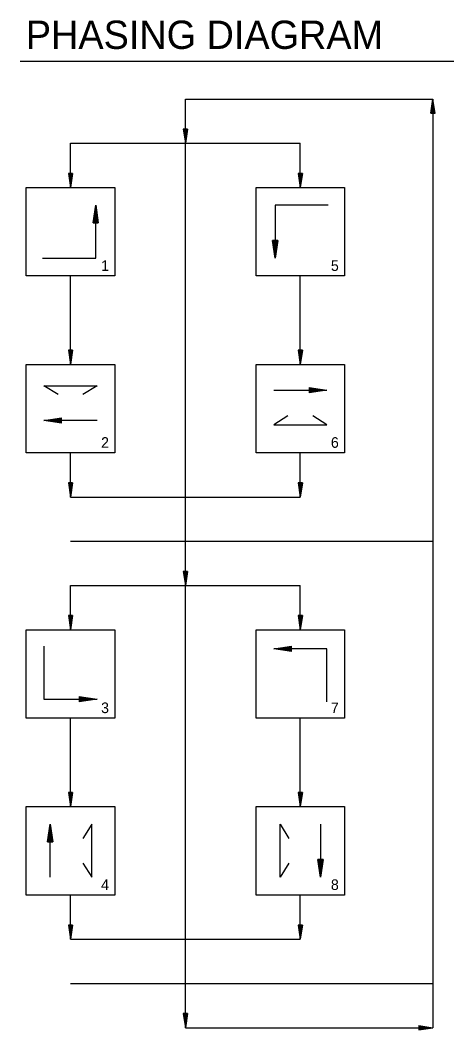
# Model space of a CAD drawing. Extents: x -19.5 to 29.5, y 0.4 to 10.6.
# Drawn here: x 1.101 to 3.145, y 5.812 to 10.569 of the extents above; entities that cross this region are included whole.
import ezdxf

# ---------------------------------------------------------------- set-up
doc = ezdxf.new("R2010")
doc.units = 0
for name, color, linetype in [('R_Draft', 7, 'Continuous'), ('T_Drafting', 7, 'Continuous'), ('T_Notes', 7, 'Continuous')]:
    doc.layers.add(name, color=color, linetype=linetype)

msp = doc.modelspace()

# ---------------------------------------------------------------- linework, layer by layer
at = {"layer": 'R_Draft'}
for p, q in [((3.0364, 10.1308), (3.0464, 10.1974)), ((3.0381, 10.1308), (3.0464, 10.1863)), ((3.0564, 10.1308), (3.0464, 10.1974)), ((3.0548, 10.1308), (3.0464, 10.1863)), ((3.0398, 10.1308), (3.0464, 10.1748)), ((3.0415, 10.1308), (3.0464, 10.1637)), ((3.0432, 10.1308), (3.0464, 10.1524)), ((3.0449, 10.1308), (3.0464, 10.1413)), ((3.0531, 10.1308), (3.0464, 10.1748)), ((3.0514, 10.1308), (3.0464, 10.1637)), ((3.0497, 10.1308), (3.0464, 10.1524)), ((3.048, 10.1308), (3.0464, 10.1413)), ((3.0364, 10.1308), (3.0564, 10.1308)), ((1.8698, 10.0558), (1.8798, 9.9891)), ((1.8898, 10.0558), (1.8698, 10.0558)), ((1.8714, 10.0558), (1.8798, 10.0002)), ((1.8731, 10.0558), (1.8798, 10.0117)), ((1.8748, 10.0558), (1.8798, 10.0228)), ((1.8765, 10.0558), (1.8798, 10.0341)), ((1.8782, 10.0558), (1.8798, 10.0452)), ((1.8898, 10.0558), (1.8798, 9.9891)), ((1.883, 10.0558), (1.8798, 10.0341)), ((1.8864, 10.0558), (1.8798, 10.0117)), ((1.8881, 10.0558), (1.8798, 10.0002)), ((1.8847, 10.0558), (1.8798, 10.0228)), ((1.8813, 10.0558), (1.8798, 10.0452)), ((1.3281, 9.8474), (1.3381, 9.7808)), ((1.3481, 9.8474), (1.3281, 9.8474)), ((1.3298, 9.8474), (1.3381, 9.7919)), ((1.3315, 9.8474), (1.3381, 9.8034)), ((1.3331, 9.8474), (1.3381, 9.8145)), ((1.3348, 9.8474), (1.3381, 9.8258)), ((1.3365, 9.8474), (1.3381, 9.8369)), ((1.3481, 9.8474), (1.3381, 9.7808)), ((1.3413, 9.8474), (1.3381, 9.8258)), ((1.3447, 9.8474), (1.3381, 9.8034)), ((1.3464, 9.8474), (1.3381, 9.7919)), ((1.3431, 9.8474), (1.3381, 9.8145)), ((1.3397, 9.8474), (1.3381, 9.8369)), ((2.4114, 9.8474), (2.4214, 9.7808)), ((2.4314, 9.8474), (2.4114, 9.8474)), ((2.4131, 9.8474), (2.4214, 9.7919)), ((2.4148, 9.8474), (2.4214, 9.8034)), ((2.4165, 9.8474), (2.4214, 9.8145)), ((2.4182, 9.8474), (2.4214, 9.8258)), ((2.4199, 9.8474), (2.4214, 9.8369)), ((2.4314, 9.8474), (2.4214, 9.7808)), ((2.4247, 9.8474), (2.4214, 9.8258)), ((2.4281, 9.8474), (2.4214, 9.8034)), ((2.4298, 9.8474), (2.4214, 9.7919)), ((2.4264, 9.8474), (2.4214, 9.8145)), ((2.423, 9.8474), (2.4214, 9.8369)), ((1.3281, 9.0141), (1.3381, 8.9474)), ((1.3481, 9.0141), (1.3281, 9.0141)), ((1.3298, 9.0141), (1.3381, 8.9586)), ((1.3315, 9.0141), (1.3381, 8.97)), ((1.3331, 9.0141), (1.3381, 8.9811)), ((1.3348, 9.0141), (1.3381, 8.9924)), ((1.3365, 9.0141), (1.3381, 9.0036)), ((1.3481, 9.0141), (1.3381, 8.9474)), ((1.3413, 9.0141), (1.3381, 8.9924)), ((1.3447, 9.0141), (1.3381, 8.97)), ((1.3464, 9.0141), (1.3381, 8.9586)), ((1.3431, 9.0141), (1.3381, 8.9811)), ((1.3397, 9.0141), (1.3381, 9.0036)), ((2.4114, 9.0141), (2.4214, 8.9474)), ((2.4314, 9.0141), (2.4114, 9.0141)), ((2.4131, 9.0141), (2.4214, 8.9586)), ((2.4148, 9.0141), (2.4214, 8.97)), ((2.4165, 9.0141), (2.4214, 8.9811)), ((2.4182, 9.0141), (2.4214, 8.9924)), ((2.4199, 9.0141), (2.4214, 9.0036)), ((2.4314, 9.0141), (2.4214, 8.9474)), ((2.4247, 9.0141), (2.4214, 8.9924)), ((2.4281, 9.0141), (2.4214, 8.97)), ((2.4298, 9.0141), (2.4214, 8.9586)), ((2.4264, 9.0141), (2.4214, 8.9811)), ((2.423, 9.0141), (2.4214, 9.0036)), ((1.3281, 8.3891), (1.3381, 8.3224)), ((1.3481, 8.3891), (1.3281, 8.3891)), ((1.3298, 8.3891), (1.3381, 8.3336)), ((1.3315, 8.3891), (1.3381, 8.345)), ((1.3331, 8.3891), (1.3381, 8.3561)), ((1.3348, 8.3891), (1.3381, 8.3674)), ((1.3365, 8.3891), (1.3381, 8.3786)), ((1.3481, 8.3891), (1.3381, 8.3224)), ((1.3413, 8.3891), (1.3381, 8.3674)), ((1.3447, 8.3891), (1.3381, 8.345)), ((1.3464, 8.3891), (1.3381, 8.3336)), ((1.3431, 8.3891), (1.3381, 8.3561)), ((1.3397, 8.3891), (1.3381, 8.3786)), ((2.4114, 8.3891), (2.4214, 8.3224)), ((2.4314, 8.3891), (2.4114, 8.3891)), ((2.4131, 8.3891), (2.4214, 8.3336)), ((2.4148, 8.3891), (2.4214, 8.345)), ((2.4165, 8.3891), (2.4214, 8.3561)), ((2.4182, 8.3891), (2.4214, 8.3674)), ((2.4199, 8.3891), (2.4214, 8.3786)), ((2.4314, 8.3891), (2.4214, 8.3224)), ((2.4247, 8.3891), (2.4214, 8.3674)), ((2.4281, 8.3891), (2.4214, 8.345)), ((2.4298, 8.3891), (2.4214, 8.3336)), ((2.4264, 8.3891), (2.4214, 8.3561)), ((2.423, 8.3891), (2.4214, 8.3786)), ((1.8698, 7.9724), (1.8798, 7.9058)), ((1.8898, 7.9724), (1.8698, 7.9724)), ((1.8714, 7.9724), (1.8798, 7.9169)), ((1.8731, 7.9724), (1.8798, 7.9284)), ((1.8748, 7.9724), (1.8798, 7.9395)), ((1.8765, 7.9724), (1.8798, 7.9508)), ((1.8782, 7.9724), (1.8798, 7.9619)), ((1.8898, 7.9724), (1.8798, 7.9058)), ((1.883, 7.9724), (1.8798, 7.9508)), ((1.8864, 7.9724), (1.8798, 7.9284)), ((1.8881, 7.9724), (1.8798, 7.9169)), ((1.8847, 7.9724), (1.8798, 7.9395)), ((1.8813, 7.9724), (1.8798, 7.9619)), ((1.3281, 7.7641), (1.3381, 7.6974)), ((1.3481, 7.7641), (1.3281, 7.7641)), ((1.3298, 7.7641), (1.3381, 7.7086)), ((1.3315, 7.7641), (1.3381, 7.72)), ((1.3331, 7.7641), (1.3381, 7.7311)), ((1.3348, 7.7641), (1.3381, 7.7424)), ((1.3365, 7.7641), (1.3381, 7.7536)), ((1.3481, 7.7641), (1.3381, 7.6974)), ((1.3413, 7.7641), (1.3381, 7.7424)), ((1.3447, 7.7641), (1.3381, 7.72)), ((1.3464, 7.7641), (1.3381, 7.7086)), ((1.3431, 7.7641), (1.3381, 7.7311)), ((1.3397, 7.7641), (1.3381, 7.7536)), ((2.4114, 7.7641), (2.4214, 7.6974)), ((2.4314, 7.7641), (2.4114, 7.7641)), ((2.4131, 7.7641), (2.4214, 7.7086)), ((2.4148, 7.7641), (2.4214, 7.72)), ((2.4165, 7.7641), (2.4214, 7.7311)), ((2.4182, 7.7641), (2.4214, 7.7424)), ((2.4199, 7.7641), (2.4214, 7.7536)), ((2.4314, 7.7641), (2.4214, 7.6974)), ((2.4247, 7.7641), (2.4214, 7.7424)), ((2.4281, 7.7641), (2.4214, 7.72)), ((2.4298, 7.7641), (2.4214, 7.7086)), ((2.4264, 7.7641), (2.4214, 7.7311)), ((2.423, 7.7641), (2.4214, 7.7536)), ((1.3281, 6.9308), (1.3381, 6.8641)), ((1.3481, 6.9308), (1.3281, 6.9308)), ((1.3298, 6.9308), (1.3381, 6.8752)), ((1.3315, 6.9308), (1.3381, 6.8867)), ((1.3331, 6.9308), (1.3381, 6.8978)), ((1.3348, 6.9308), (1.3381, 6.9091)), ((1.3365, 6.9308), (1.3381, 6.9202)), ((1.3481, 6.9308), (1.3381, 6.8641)), ((1.3413, 6.9308), (1.3381, 6.9091)), ((1.3447, 6.9308), (1.3381, 6.8867)), ((1.3464, 6.9308), (1.3381, 6.8752)), ((1.3431, 6.9308), (1.3381, 6.8978)), ((1.3397, 6.9308), (1.3381, 6.9202)), ((2.4114, 6.9308), (2.4214, 6.8641)), ((2.4314, 6.9308), (2.4114, 6.9308)), ((2.4131, 6.9308), (2.4214, 6.8752)), ((2.4148, 6.9308), (2.4214, 6.8867)), ((2.4165, 6.9308), (2.4214, 6.8978)), ((2.4182, 6.9308), (2.4214, 6.9091)), ((2.4199, 6.9308), (2.4214, 6.9202)), ((2.4314, 6.9308), (2.4214, 6.8641)), ((2.4247, 6.9308), (2.4214, 6.9091)), ((2.4281, 6.9308), (2.4214, 6.8867)), ((2.4298, 6.9308), (2.4214, 6.8752)), ((2.4264, 6.9308), (2.4214, 6.8978)), ((2.423, 6.9308), (2.4214, 6.9202)), ((1.3281, 6.3058), (1.3381, 6.2391)), ((1.3481, 6.3058), (1.3281, 6.3058)), ((1.3298, 6.3058), (1.3381, 6.2502)), ((1.3315, 6.3058), (1.3381, 6.2617)), ((1.3331, 6.3058), (1.3381, 6.2728)), ((1.3348, 6.3058), (1.3381, 6.2841)), ((1.3365, 6.3058), (1.3381, 6.2952)), ((1.3481, 6.3058), (1.3381, 6.2391)), ((1.3413, 6.3058), (1.3381, 6.2841)), ((1.3447, 6.3058), (1.3381, 6.2617)), ((1.3464, 6.3058), (1.3381, 6.2502)), ((1.3431, 6.3058), (1.3381, 6.2728)), ((1.3397, 6.3058), (1.3381, 6.2952)), ((2.4114, 6.3058), (2.4214, 6.2391)), ((2.4314, 6.3058), (2.4114, 6.3058)), ((2.4131, 6.3058), (2.4214, 6.2502)), ((2.4148, 6.3058), (2.4214, 6.2617)), ((2.4165, 6.3058), (2.4214, 6.2728)), ((2.4182, 6.3058), (2.4214, 6.2841)), ((2.4199, 6.3058), (2.4214, 6.2952)), ((2.4314, 6.3058), (2.4214, 6.2391)), ((2.4247, 6.3058), (2.4214, 6.2841)), ((2.4281, 6.3058), (2.4214, 6.2617)), ((2.4298, 6.3058), (2.4214, 6.2502)), ((2.4264, 6.3058), (2.4214, 6.2728)), ((2.423, 6.3058), (2.4214, 6.2952)), ((1.8698, 5.8891), (1.8798, 5.8224)), ((1.8898, 5.8891), (1.8698, 5.8891)), ((1.8714, 5.8891), (1.8798, 5.8336)), ((1.8731, 5.8891), (1.8798, 5.845)), ((1.8748, 5.8891), (1.8798, 5.8561)), ((1.8765, 5.8891), (1.8798, 5.8674)), ((1.8782, 5.8891), (1.8798, 5.8786)), ((1.8898, 5.8891), (1.8798, 5.8224)), ((1.883, 5.8891), (1.8798, 5.8674)), ((1.8864, 5.8891), (1.8798, 5.845)), ((1.8881, 5.8891), (1.8798, 5.8336)), ((1.8847, 5.8891), (1.8798, 5.8561)), ((1.8813, 5.8891), (1.8798, 5.8786)), ((2.9798, 5.8324), (3.0464, 5.8224)), ((2.9798, 5.8324), (2.9798, 5.8124)), ((2.9798, 5.8308), (3.0353, 5.8224)), ((2.9798, 5.8291), (3.0238, 5.8224)), ((2.9798, 5.8274), (3.0127, 5.8224)), ((2.9798, 5.8257), (3.0014, 5.8224)), ((2.9798, 5.824), (2.9903, 5.8224)), ((2.9798, 5.8124), (3.0464, 5.8224)), ((2.9798, 5.8192), (3.0014, 5.8224)), ((2.9798, 5.8158), (3.0238, 5.8224)), ((2.9798, 5.8141), (3.0353, 5.8224)), ((2.9798, 5.8175), (3.0127, 5.8224)), ((2.9798, 5.8209), (2.9903, 5.8224))]:
    msp.add_line(p, q, dxfattribs=at)
at = {"layer": 'T_Drafting'}
for p, q in [((1.8798, 5.8224), (1.8798, 10.1974)), ((1.8798, 10.1974), (3.0464, 10.1974)), ((3.0464, 10.1974), (3.0464, 5.8224)), ((1.3381, 9.7808), (1.3381, 9.9891)), ((1.3381, 9.9891), (2.4214, 9.9891)), ((2.4214, 9.7808), (2.4214, 9.9891)), ((1.4443, 9.6141), (1.4568, 9.6974)), ((1.4568, 9.6835), (1.4464, 9.6141)), ((1.4485, 9.6141), (1.4568, 9.6692)), ((1.4568, 9.4474), (1.4568, 9.6974)), ((1.4568, 9.6974), (1.4693, 9.6141)), ((1.4673, 9.6141), (1.4568, 9.6835)), ((1.4568, 9.6692), (1.4651, 9.6141)), ((2.5527, 9.6974), (2.3027, 9.6974)), ((2.3027, 9.6974), (2.3027, 9.4474)), ((1.4443, 9.6141), (1.4693, 9.6141)), ((1.4568, 9.6553), (1.4506, 9.6141)), ((1.4528, 9.6141), (1.4568, 9.6412)), ((1.4568, 9.6273), (1.4549, 9.6141)), ((1.463, 9.6141), (1.4568, 9.6553)), ((1.4568, 9.6412), (1.4609, 9.6141)), ((1.4588, 9.6141), (1.4568, 9.6273)), ((2.3027, 9.4474), (2.2902, 9.5308)), ((2.3152, 9.5308), (2.2902, 9.5308)), ((2.2923, 9.5308), (2.3027, 9.4613)), ((2.3027, 9.4757), (2.2944, 9.5308)), ((2.2965, 9.5308), (2.3027, 9.4895)), ((2.3027, 9.5037), (2.2986, 9.5308)), ((2.3007, 9.5308), (2.3027, 9.5176)), ((2.3027, 9.5176), (2.3046, 9.5308)), ((2.3067, 9.5308), (2.3027, 9.5037)), ((2.3027, 9.4895), (2.3089, 9.5308)), ((2.311, 9.5308), (2.3027, 9.4757)), ((2.3027, 9.4613), (2.3131, 9.5308)), ((2.3152, 9.5308), (2.3027, 9.4474)), ((1.2068, 9.4474), (1.4568, 9.4474)), ((1.3381, 8.9474), (1.3381, 9.3641)), ((2.4214, 8.9474), (2.4214, 9.3641)), ((2.2964, 8.8264), (2.5464, 8.8264)), ((2.4631, 8.8389), (2.5464, 8.8264)), ((2.4631, 8.8389), (2.4631, 8.8139)), ((2.5325, 8.8264), (2.4631, 8.8368)), ((2.4631, 8.8347), (2.5182, 8.8264)), ((2.5043, 8.8264), (2.4631, 8.8326)), ((2.4631, 8.8304), (2.4902, 8.8264)), ((2.4763, 8.8264), (2.4631, 8.8283)), ((2.5464, 8.8264), (2.4631, 8.8139)), ((2.4631, 8.8159), (2.5325, 8.8264)), ((2.5182, 8.8264), (2.4631, 8.8181)), ((2.4631, 8.8202), (2.5043, 8.8264)), ((2.4902, 8.8264), (2.4631, 8.8223)), ((2.4631, 8.8244), (2.4763, 8.8264)), ((1.2131, 8.6838), (1.2964, 8.6963)), ((1.4631, 8.6838), (1.2131, 8.6838)), ((1.2964, 8.6713), (1.2131, 8.6838)), ((1.2964, 8.6942), (1.227, 8.6838)), ((1.227, 8.6838), (1.2964, 8.6734)), ((1.2413, 8.6838), (1.2964, 8.6921)), ((1.2964, 8.6755), (1.2413, 8.6838)), ((1.2964, 8.69), (1.2552, 8.6838)), ((1.2552, 8.6838), (1.2964, 8.6776)), ((1.2693, 8.6838), (1.2964, 8.6879)), ((1.2964, 8.6798), (1.2693, 8.6838)), ((1.2964, 8.6858), (1.2833, 8.6838)), ((1.2833, 8.6838), (1.2964, 8.6819)), ((1.2964, 8.6713), (1.2964, 8.6963)), ((1.3381, 8.3224), (1.3381, 8.5308)), ((2.4214, 8.3224), (2.4214, 8.5308)), ((1.3381, 8.3224), (2.4214, 8.3224)), ((1.3381, 8.1141), (3.0464, 8.1141)), ((1.3381, 7.9058), (2.4214, 7.9058)), ((1.3381, 7.6974), (1.3381, 7.9058)), ((2.4214, 7.6974), (2.4214, 7.9058)), ((1.2131, 7.6203), (1.2131, 7.3703)), ((2.2964, 7.6078), (2.3798, 7.6203)), ((2.3798, 7.6183), (2.3103, 7.6078)), ((2.3247, 7.6078), (2.3798, 7.6161)), ((2.3798, 7.614), (2.3385, 7.6078)), ((2.3527, 7.6078), (2.3798, 7.6119)), ((2.3798, 7.5953), (2.3798, 7.6203)), ((2.5464, 7.6078), (2.2964, 7.6078)), ((2.3798, 7.5953), (2.2964, 7.6078)), ((2.3103, 7.6078), (2.3798, 7.5974)), ((2.3798, 7.5995), (2.3247, 7.6078)), ((2.3385, 7.6078), (2.3798, 7.6016)), ((2.3798, 7.6038), (2.3527, 7.6078)), ((2.3798, 7.6098), (2.3666, 7.6078)), ((2.3666, 7.6078), (2.3798, 7.6059)), ((2.5464, 7.3578), (2.5464, 7.6078)), ((1.3798, 7.3828), (1.4631, 7.3703)), ((1.3798, 7.3828), (1.3798, 7.3578)), ((1.4492, 7.3703), (1.3798, 7.3808)), ((1.3798, 7.3786), (1.4348, 7.3703)), ((1.421, 7.3703), (1.3798, 7.3765)), ((1.3798, 7.3744), (1.4068, 7.3703)), ((1.2131, 7.3703), (1.4631, 7.3703)), ((1.3929, 7.3703), (1.3798, 7.3723)), ((1.4631, 7.3703), (1.3798, 7.3578)), ((1.3798, 7.3599), (1.4492, 7.3703)), ((1.4348, 7.3703), (1.3798, 7.362)), ((1.3798, 7.3641), (1.421, 7.3703)), ((1.4068, 7.3703), (1.3798, 7.3663)), ((1.3798, 7.3684), (1.3929, 7.3703)), ((1.3381, 6.8641), (1.3381, 7.2808)), ((2.4214, 6.8641), (2.4214, 7.2808)), ((1.2303, 6.6974), (1.2428, 6.7808)), ((1.2428, 6.7668), (1.2323, 6.6974)), ((1.2428, 6.5308), (1.2428, 6.7808)), ((1.2428, 6.7808), (1.2553, 6.6974)), ((1.2532, 6.6974), (1.2428, 6.7668)), ((2.5167, 6.7808), (2.5167, 6.5308)), ((1.2345, 6.6974), (1.2428, 6.7525)), ((1.2428, 6.7386), (1.2366, 6.6974)), ((1.2387, 6.6974), (1.2428, 6.7245)), ((1.2428, 6.7106), (1.2408, 6.6974)), ((1.2428, 6.7525), (1.2511, 6.6974)), ((1.249, 6.6974), (1.2428, 6.7386)), ((1.2428, 6.7245), (1.2468, 6.6974)), ((1.2447, 6.6974), (1.2428, 6.7106)), ((1.2303, 6.6974), (1.2553, 6.6974)), ((2.5167, 6.5308), (2.5042, 6.6141)), ((2.5292, 6.6141), (2.5042, 6.6141)), ((2.5063, 6.6141), (2.5167, 6.5447)), ((2.5167, 6.559), (2.5084, 6.6141)), ((2.5105, 6.6141), (2.5167, 6.5729)), ((2.5167, 6.587), (2.5127, 6.6141)), ((2.5148, 6.6141), (2.5167, 6.6009)), ((2.5167, 6.6009), (2.5187, 6.6141)), ((2.5208, 6.6141), (2.5167, 6.587)), ((2.5167, 6.5729), (2.5229, 6.6141)), ((2.525, 6.6141), (2.5167, 6.559)), ((2.5167, 6.5447), (2.5272, 6.6141)), ((2.5292, 6.6141), (2.5167, 6.5308)), ((1.3381, 6.2391), (1.3381, 6.4474)), ((2.4214, 6.2391), (2.4214, 6.4474)), ((1.3381, 6.2391), (2.4214, 6.2391)), ((1.3381, 6.0308), (3.0464, 6.0308)), ((1.8798, 5.8224), (3.0464, 5.8224))]:
    msp.add_line(p, q, dxfattribs=at)
for points in [[(1.1298, 9.7808), (1.5464, 9.7808), (1.5464, 9.3641), (1.1298, 9.3641)], [(2.2131, 9.7808), (2.6298, 9.7808), (2.6298, 9.3641), (2.2131, 9.3641)], [(1.1298, 8.9474), (1.5464, 8.9474), (1.5464, 8.5308), (1.1298, 8.5308)], [(2.2131, 8.9474), (2.6298, 8.9474), (2.6298, 8.5308), (2.2131, 8.5308)], [(1.1298, 7.6974), (1.5464, 7.6974), (1.5464, 7.2808), (1.1298, 7.2808)], [(2.2131, 7.6974), (2.6298, 7.6974), (2.6298, 7.2808), (2.2131, 7.2808)], [(1.1298, 6.8641), (1.5464, 6.8641), (1.5464, 6.4474), (1.1298, 6.4474)], [(2.2131, 6.8641), (2.6298, 6.8641), (2.6298, 6.4474), (2.2131, 6.4474)]]:
    msp.add_lwpolyline(points, close=True, dxfattribs=at)
for points in [[(1.2798, 8.8055), (1.2131, 8.8472), (1.4631, 8.8472), (1.3964, 8.8055)], [(2.3631, 8.7046), (2.2964, 8.663), (2.5464, 8.663), (2.4798, 8.7046)], [(1.3967, 6.5974), (1.4383, 6.5308), (1.4383, 6.7808), (1.3967, 6.7141)], [(2.3678, 6.5974), (2.3261, 6.5308), (2.3261, 6.7808), (2.3678, 6.7141)]]:
    msp.add_lwpolyline(points, dxfattribs=at)
at = {"layer": 'T_Notes'}
msp.add_line((1.101, 10.376), (3.1451, 10.376), dxfattribs=at)

# ---------------------------------------------------------------- texts
for s, height, p in [('PHASING DIAGRAM', 0.133333, (1.1276, 10.4338)), ('1', 0.05, (1.4824, 9.3878)), ('5', 0.05, (2.5657, 9.3878)), ('2', 0.05, (1.4824, 8.5545)), ('6', 0.05, (2.5657, 8.5545)), ('3', 0.05, (1.4824, 7.3045)), ('7', 0.05, (2.5657, 7.3045)), ('4', 0.05, (1.4824, 6.4711)), ('8', 0.05, (2.5657, 6.4711))]:
    msp.add_text(s, height=height, dxfattribs=at).set_placement(p)

doc.saveas('drawing.dxf')
